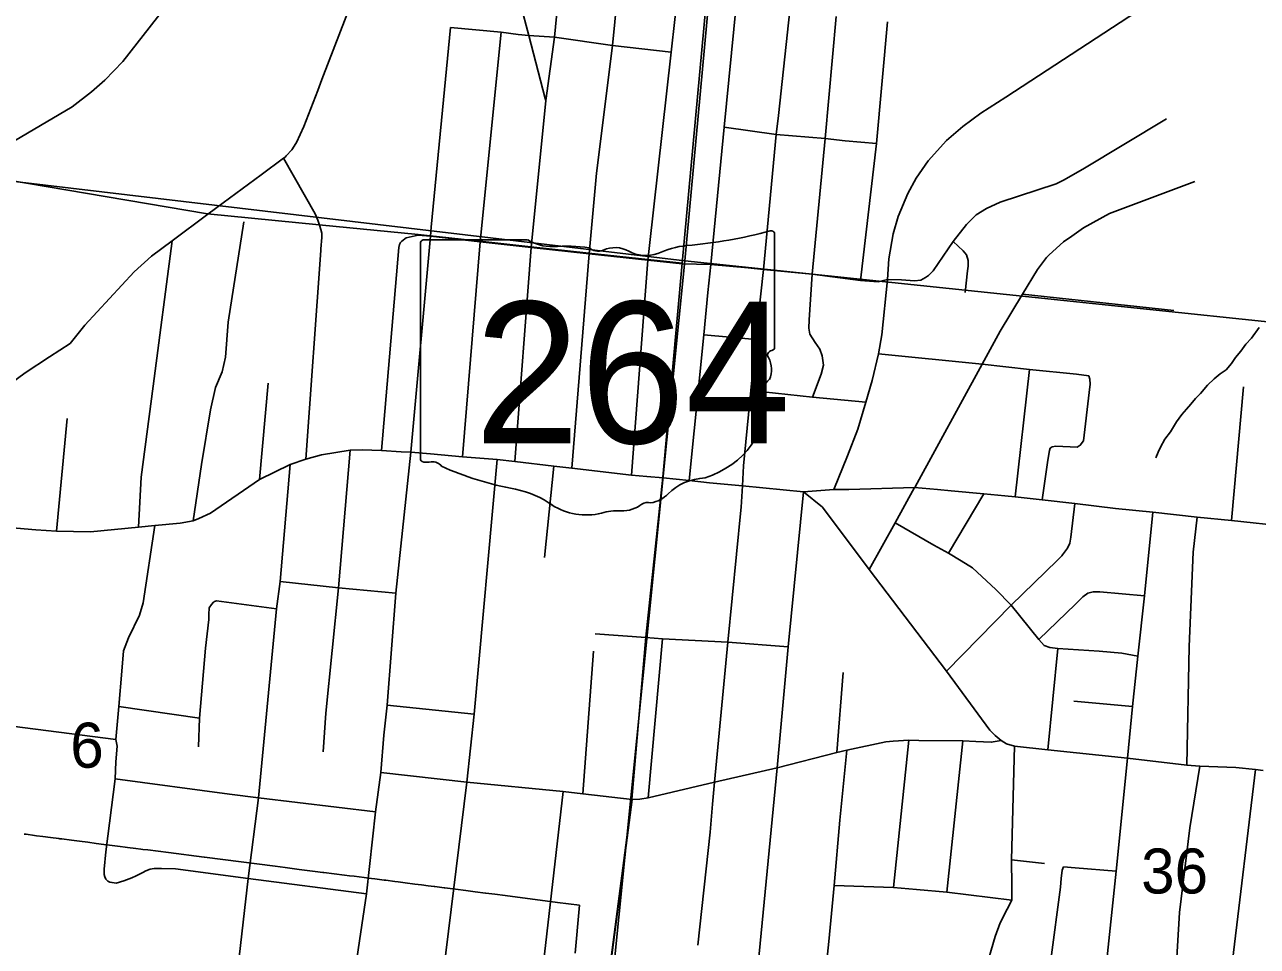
# Model space of a CAD drawing. Extents: x -8.2 to 38.5, y -0.1 to 21.9.
# Drawn here: x 2.928 to 4.076, y 14.657 to 15.515 of the extents above; entities that cross this region are included whole.
import ezdxf

# ---------------------------------------------------------------- set-up
doc = ezdxf.new("R2010")
doc.units = 0
for name, color, linetype in [('Default', 7, 'Continuous'), ('GM_X_Adjacent_County_Text', 7, 'Continuous'), ('GM_X_Airport_Location_Class_1', 7, 'Continuous'), ('GM_X_County_Road_Text', 7, 'Continuous'), ('GM_X_Major_River', 7, 'Continuous'), ('GM_X_Minor_River', 7, 'Continuous'), ('GM_X_Township_Subdivision_Text', 7, 'Continuous'), ('GM_X_Township_Text', 7, 'Continuous')]:
    doc.layers.add(name, color=color, linetype=linetype)

msp = doc.modelspace()

# ---------------------------------------------------------------- linework, layer by layer
at = {"layer": 'Default'}
for points in [[(3.6725, 16.67), (3.6705, 16.651), (3.6688, 16.6346), (3.6178, 16.1066), (3.5847, 15.7703), (3.5728, 15.6426), (3.5629, 15.5356), (3.5403, 15.2932), (3.5225, 15.0941), (3.5065, 14.9452), (3.4936, 14.7944), (3.4743, 14.647), (3.4653, 14.578), (3.4343, 14.2388), (3.4223, 14.1017), (3.4095, 13.9645), (4.8235, 13.9645)], [(2.8549, 15.3805), (3.0986, 15.3393), (3.2027, 15.3291), (3.2946, 15.3201), (3.3059, 15.3188), (3.3521, 15.3138), (3.3997, 15.3085), (3.4537, 15.3026), (3.5084, 15.2966), (3.5403, 15.2932), (3.5629, 15.5356), (3.5728, 15.6426), (3.5847, 15.7703), (3.6178, 16.1066), (3.6688, 16.6346)], [(3.4743, 14.647), (3.4936, 14.7944), (3.5065, 14.9452), (3.5225, 15.0941), (3.5403, 15.2932), (3.5084, 15.2966), (3.4537, 15.3026), (3.3997, 15.3085), (3.3521, 15.3138), (3.3059, 15.3188), (3.2946, 15.3201), (3.2027, 15.3291), (3.0986, 15.3393), (2.8549, 15.3805), (2.6397, 15.4029), (2.5303, 15.4164), (2.483, 15.4176), (2.4275, 15.419), (2.3952, 15.4189), (2.3338, 15.4222), (2.1974, 15.4294), (2.1644, 15.4316), (2.1634, 15.4317), (2.1634, 13.9645)], [(2.928, 14.7618), (2.9291, 14.7617), (2.9299, 14.7616), (2.9377, 14.7606), (2.9396, 14.7603), (2.9453, 14.7596), (2.9526, 14.7587), (2.9602, 14.7577), (2.9613, 14.7575), (2.9629, 14.7573), (2.9722, 14.7561), (2.9796, 14.7552), (2.9874, 14.7542), (2.995, 14.7532), (3.0023, 14.7522), (3.0098, 14.7512), (3.0173, 14.7503), (3.0219, 14.7497), (3.0243, 14.7494), (3.0318, 14.7484), (3.0366, 14.7478), (3.0385, 14.7476), (3.0432, 14.747), (3.0623, 14.7446), (3.0955, 14.7403), (3.0959, 14.7402), (3.1615, 14.7318), (3.1709, 14.7306), (3.1838, 14.7289), (3.1988, 14.7271), (3.2061, 14.7262), (3.2069, 14.7261), (3.2262, 14.7236), (3.2307, 14.7231), (3.2352, 14.7225), (3.2445, 14.7214), (3.2514, 14.7205), (3.2544, 14.7201), (3.2631, 14.719), (3.2645, 14.7189), (3.273, 14.7178), (3.276, 14.7174), (3.2805, 14.7168), (3.2825, 14.7165), (3.2917, 14.7153), (3.2977, 14.7145), (3.304, 14.7137), (3.3096, 14.713), (3.3101, 14.7129), (3.3188, 14.7118), (3.3193, 14.7117), (3.3196, 14.7117), (3.3294, 14.7104), (3.3392, 14.7092), (3.3477, 14.7081), (3.3574, 14.7069), (3.3576, 14.7069), (3.3662, 14.7058), (3.3758, 14.7045), (3.4243, 14.6982), (3.4448, 14.6955), (3.4445, 14.6922), (3.4409, 14.651)]]:
    msp.add_lwpolyline(points, dxfattribs=at)
at = {"layer": 'GM_X_Adjacent_County_Text'}
for points in [[(3.6356, 16.3025), (3.5428, 15.2954), (2.5334, 15.4148), (2.633, 16.4084)], [(4.6267, 16.1928), (4.5212, 15.1931), (3.5428, 15.2954), (3.6356, 16.3025)], [(2.5334, 15.4148), (3.5428, 15.2954), (3.4423, 14.2958), (2.4212, 14.4207)], [(3.5428, 15.2954), (4.5212, 15.1931), (4.4166, 14.1829), (3.4423, 14.2958)]]:
    msp.add_lwpolyline(points, close=True, dxfattribs=at)
at = {"layer": 'GM_X_Airport_Location_Class_1'}
msp.add_line((3.6533, 15.0805), (3.6817, 15.0826), dxfattribs=at)
for points in [[(2.9138, 15.0473), (2.9388, 15.0449), (2.9582, 15.0439), (2.9897, 15.0433), (3.0344, 15.0476), (3.0496, 15.049), (3.0732, 15.0513), (3.0853, 15.0535), (3.0906, 15.0555), (3.1013, 15.0607), (3.1471, 15.092), (3.1756, 15.106), (3.1903, 15.1108), (3.2047, 15.1148), (3.2313, 15.1192), (3.2427, 15.1196), (3.2607, 15.1189), (3.2789, 15.1178)], [(3.2789, 15.1178), (3.2879, 15.1173), (3.3063, 15.1159), (3.336, 15.113), (3.3683, 15.1104), (3.3847, 15.1086), (3.4211, 15.1044), (3.4376, 15.1023), (3.4933, 15.0959)], [(3.4933, 15.0959), (3.5074, 15.0948), (3.5227, 15.0936), (3.5469, 15.091), (3.5658, 15.0888), (3.5966, 15.086), (3.6533, 15.0805)], [(3.6817, 15.0826), (3.6954, 15.0826), (3.7568, 15.0845), (3.778, 15.0826)], [(3.778, 15.0826), (3.7907, 15.0814), (3.8213, 15.0787), (3.8406, 15.0766), (3.8502, 15.0757), (3.8755, 15.0729), (3.9058, 15.0697), (3.9437, 15.0648), (3.9786, 15.0615), (4.0197, 15.0569), (4.0518, 15.0538), (4.1035, 15.0481)]]:
    msp.add_lwpolyline(points, dxfattribs=at)
at = {"layer": 'GM_X_Major_River'}
for p, q in [((3.6265, 15.2153), (3.6265, 15.32)), ((3.2969, 15.3116), (3.2969, 15.1115)), ((3.3966, 15.3151), (3.3001, 15.3151)), ((3.6264, 15.2154), (3.6265, 15.2153))]:
    msp.add_line(p, q, dxfattribs=at)
for centre, major_axis, start_param, end_param in [((3.5091, 15.5879), (0.3495, 0), 4.814394, 5.042369), ((3.6228, 15.3205), (0.00367, 0), 6.141152, 7.989035), ((3.3007, 15.312), (0.00382, 0), 1.712693, 3.28349), ((3.4196, 15.3383), (0.037, 0), 4.042523, 4.731795), ((3.4319, 15.2027), (0.133, 0), 1.404758, 1.657858), ((3.4621, 15.3131), (0.0107, 0), 3.836095, 5.185415), ((3.4778, 15.29), (0.0222, 0), 0.950623, 2.079405), ((3.5536, 15.2539), (0.0703, 0), 1.699011, 2.107814), ((3.5065, 15.3217), (0.0267, 0), 4.081561, 5.145723), ((3.6226, 15.2149), (0.00393, 0), 5.05454, 6.418171), ((3.6256, 15.2077), (0.00568, 0), 1.883978, 3.671073), ((3.5895, 15.1944), (0.0341, 0), 5.934695, 6.695948), ((3.6396, 15.1715), (0.0248, 0), 2.387724, 3.262537), ((3.5286, 15.1582), (0.0874, 0), 5.101752, 6.440018), ((3.3007, 15.1111), (0.00385, 0), 3.00124, 4.508301), ((3.3013, 15.1315), (0.0294, 0), 4.665946, 4.897461), ((3.3073, 15.1), (0.0106, 0), 0.519207, 1.627899), ((3.4411, 15.2798), (0.2524, 0), 4.195997, 4.488961), ((3.5655, 15.0553), (0.0479, 0), 1.647645, 2.488434), ((3.3659, 15.0216), (0.079, 0), 0.823519, 1.323587), ((3.5048, 15.0921), (0.0282, 0), 4.937069, 5.64225), ((3.4513, 15.099), (0.0501, 0), 4.026481, 4.996735), ((3.4839, 15.084), (0.0267, 0), 4.691044, 5.507374), ((3.508, 15.0646), (0.00752, 0), 1.147584, 2.315152), ((3.4802, 15.0298), (0.0412, 0), 1.495662, 1.94098)]:
    msp.add_ellipse(centre, major_axis=major_axis, ratio=0.8, start_param=start_param, end_param=end_param, dxfattribs=at)
at = {"layer": 'GM_X_Minor_River'}
msp.add_lwpolyline([(4.0773, 15.2335), (4.0702, 15.2234), (4.0651, 15.2178), (4.0604, 15.2115), (4.0553, 15.2055), (4.0517, 15.1999), (4.0466, 15.194), (4.0411, 15.1903), (4.0357, 15.1855), (4.0294, 15.1796), (4.0228, 15.1721), (4.0181, 15.1673), (4.0138, 15.1621), (4.0098, 15.1573), (4.0055, 15.1524), (4.0004, 15.1457), (3.9948, 15.1364), (3.9897, 15.1296), (3.9857, 15.1221), (3.9836, 15.1172), (3.9812, 15.112)], dxfattribs=at)
at = {"layer": 'GM_X_Township_Subdivision_Text'}
for p, q in [((3.8572, 15.2644), (3.998, 15.2493)), ((3.5607, 15.2265), (3.6091, 15.2221)), ((3.8502, 15.0757), (3.8636, 15.1943)), ((3.1471, 15.092), (3.155, 15.1816)), ((4.0518, 15.0538), (4.0629, 15.1781)), ((2.9582, 15.0439), (2.9679, 15.1488)), ((3.4122, 15.0193), (3.4211, 15.1044)), ((3.7883, 15.0232), (3.8213, 15.0787)), ((3.5089, 14.7957), (3.522, 14.9436)), ((3.448, 14.7992), (3.4578, 14.9322)), ((3.8807, 14.8402), (3.8902, 14.9347)), ((3.6844, 14.8377), (3.6902, 14.9122)), ((3.0162, 14.8806), (3.0913, 14.8697)), ((3.2659, 14.8817), (3.3469, 14.8734)), ((3.905, 14.8856), (3.9597, 14.8807)), ((3.737, 14.712), (3.7515, 14.8492)), ((3.7867, 14.7077), (3.8017, 14.8485)), ((3.3141, 14.5989), (3.3401, 14.8102)), ((3.4051, 14.5862), (3.4296, 14.8014)), ((3.8469, 14.7378), (3.8775, 14.7345))]:
    msp.add_line(p, q, dxfattribs=at)
for points in [[(3.4933, 15.0959), (3.5086, 15.2961), (3.5096, 15.307), (3.5303, 15.4898), (3.5337, 15.5201), (3.5471, 15.6449), (3.5528, 15.7067), (3.5548, 15.7184), (3.5563, 15.7322), (3.5573, 15.7484), (3.5547, 15.7717)], [(3.4136, 15.4446), (3.4215, 15.5038), (3.4364, 15.6582)], [(3.4376, 15.1023), (3.4539, 15.3021), (3.4607, 15.377), (3.4755, 15.4959), (3.4907, 15.6506)], [(3.3847, 15.1086), (3.4, 15.308), (3.4136, 15.4446), (3.413, 15.4465), (3.3978, 15.5051), (3.39, 15.5345), (3.3858, 15.5462), (3.3784, 15.565), (3.3321, 15.6094), (3.3235, 15.6146), (3.2677, 15.648)], [(3.5469, 15.091), (3.5607, 15.2265), (3.5642, 15.2661), (3.5672, 15.2922), (3.5794, 15.4199), (3.5908, 15.5333), (3.6005, 15.6386), (3.6009, 15.6428), (3.6019, 15.6486)], [(3.5953, 15.0662), (3.5966, 15.086), (3.5976, 15.1046), (3.6044, 15.1749), (3.6091, 15.2221), (3.6161, 15.2874), (3.628, 15.4132), (3.6302, 15.4308), (3.6405, 15.5285), (3.65, 15.6286), (3.6507, 15.6346), (3.6509, 15.6387), (3.6508, 15.6416), (3.6492, 15.6437)], [(3.2879, 15.1173), (3.3061, 15.3183), (3.3069, 15.3268), (3.3249, 15.5126)], [(3.3249, 15.5126), (3.3721, 15.5082), (3.3878, 15.5061), (3.3978, 15.5051), (3.4215, 15.5038), (3.4755, 15.4959), (3.5303, 15.4898)], [(3.6836, 15.5229), (3.6735, 15.4093), (3.6614, 15.2829)], [(3.7063, 15.2771), (3.7212, 15.4047), (3.7315, 15.5181)], [(3.336, 15.113), (3.3524, 15.3132), (3.3721, 15.5082)], [(3.5794, 15.4199), (3.628, 15.4132), (3.6735, 15.4093), (3.6922, 15.4073), (3.7212, 15.4047)], [(3.7316, 15.2781), (3.7445, 15.2778), (3.7566, 15.2768), (3.7624, 15.2776), (3.7668, 15.2799), (3.7697, 15.2818), (3.7739, 15.286), (3.7786, 15.2931), (3.7925, 15.3135), (3.8052, 15.3294), (3.8087, 15.3331), (3.814, 15.3382), (3.8236, 15.3441), (3.8363, 15.3501), (3.8885, 15.3672), (3.8952, 15.3707), (3.9134, 15.3807), (3.9913, 15.4277)], [(3.2042, 15.3067), (3.2051, 15.3173), (3.2049, 15.3211), (3.204, 15.3247), (3.2029, 15.3286), (3.2012, 15.3333), (3.1987, 15.3392), (3.1693, 15.3909)], [(3.7145, 15.008), (3.7387, 15.0515), (3.7568, 15.0845), (3.7572, 15.0852), (3.8197, 15.1993), (3.8365, 15.2301), (3.8572, 15.2644), (3.871, 15.2874), (3.8794, 15.2985), (3.8821, 15.3012), (3.8954, 15.3131), (3.903, 15.3184), (3.914, 15.3261), (3.938, 15.3394), (4.0177, 15.3694)], [(3.0853, 15.0535), (3.093, 15.106), (3.1013, 15.1567), (3.106, 15.1774), (3.1122, 15.1921), (3.1155, 15.2057), (3.1179, 15.2383), (3.1324, 15.3319)], [(3.2607, 15.1189), (3.2766, 15.308), (3.2772, 15.3106), (3.2782, 15.3124), (3.2795, 15.3138), (3.2834, 15.3169)], [(3.2834, 15.3169), (3.2948, 15.3195), (3.3061, 15.3183), (3.3524, 15.3132), (3.4, 15.308), (3.4539, 15.3021), (3.5086, 15.2961), (3.5405, 15.2926), (3.5672, 15.2922), (3.6017, 15.2888), (3.6161, 15.2874), (3.6614, 15.2829), (3.7063, 15.2771), (3.7227, 15.276), (3.7316, 15.2781)], [(3.0344, 15.0476), (3.0369, 15.094), (3.0482, 15.1787), (3.0656, 15.3141)], [(3.1903, 15.1108), (3.204, 15.305), (3.2042, 15.3067)], [(3.8038, 15.2659), (3.8061, 15.2861), (3.8066, 15.2905), (3.8066, 15.2957), (3.805, 15.301), (3.802, 15.3047), (3.7925, 15.3135)], [(3.6616, 15.1687), (3.6697, 15.19), (3.6719, 15.1982), (3.6706, 15.2071), (3.6685, 15.2131), (3.6642, 15.2193), (3.6593, 15.2271), (3.6582, 15.2327), (3.6585, 15.2404), (3.6614, 15.2829)], [(3.7232, 15.209), (3.8197, 15.1993), (3.8636, 15.1943), (3.9073, 15.1899), (3.9188, 15.1885)], [(3.9081, 15.1219), (3.911, 15.1238), (3.9138, 15.128), (3.9192, 15.1729), (3.9201, 15.1806), (3.92, 15.1852), (3.9188, 15.1885)], [(3.6044, 15.1749), (3.6616, 15.1687), (3.7113, 15.164)], [(3.8755, 15.0729), (3.8809, 15.1099), (3.8824, 15.1188), (3.8829, 15.121), (3.8847, 15.1223), (3.8883, 15.123), (3.9081, 15.1219)], [(3.2062, 14.8384), (3.2087, 14.8743), (3.2205, 14.9911), (3.2313, 15.1192)], [(3.3401, 14.8102), (3.3469, 14.8734), (3.3683, 15.1104)], [(3.1258, 14.6283), (3.1364, 14.7204), (3.146, 14.7957), (3.1627, 14.9716), (3.1664, 14.9968), (3.1756, 15.106)], [(3.5688, 14.7898), (3.5705, 14.8101), (3.5828, 14.9406), (3.5951, 15.0633), (3.5953, 15.0662)], [(3.7864, 14.9134), (3.8465, 14.9748), (3.8893, 15.0166), (3.8938, 15.0209), (3.8944, 15.0217), (3.899, 15.0279), (3.9012, 15.0325), (3.9022, 15.0381), (3.9058, 15.0697)], [(3.9132, 14.4215), (3.9229, 14.5238), (3.9443, 14.7273), (3.9549, 14.8325), (3.9597, 14.8807), (3.9646, 14.9273), (3.9708, 14.9837), (3.9786, 15.0615)], [(4.01, 14.8261), (4.0124, 14.9363), (4.0161, 15.0243), (4.0197, 15.0569)], [(3.0058, 14.7181), (3.004, 14.7199), (3.003, 14.722), (3.0026, 14.7243), (3.0025, 14.7269), (3.0026, 14.7292), (3.0041, 14.7452), (3.0126, 14.8131), (3.0134, 14.8291), (3.0147, 14.8437), (3.0132, 14.8499), (3.0162, 14.8806), (3.0189, 14.9135), (3.0206, 14.9324), (3.0252, 14.9444), (3.0354, 14.9657), (3.0388, 14.977), (3.0496, 15.049)], [(3.9646, 14.9273), (3.9497, 14.9302), (3.9285, 14.932), (3.8902, 14.9347), (3.8826, 14.9354), (3.8774, 14.9374), (3.8724, 14.943), (3.8465, 14.9748), (3.8325, 14.9895), (3.8105, 15.0097), (3.8002, 15.0163), (3.7883, 15.0232), (3.7747, 15.0307), (3.7387, 15.0515)], [(3.1664, 14.9968), (3.2205, 14.9911), (3.274, 14.9861)], [(3.8724, 14.943), (3.9066, 14.976), (3.9132, 14.9828), (3.9181, 14.986), (3.9229, 14.9872), (3.9293, 14.9874), (3.9708, 14.9837)], [(3.0904, 14.8431), (3.0913, 14.8697), (3.0969, 14.9349), (3.0998, 14.9615), (3.0998, 14.9663), (3.1001, 14.9724)], [(3.1001, 14.9724), (3.1025, 14.9756), (3.1043, 14.9776), (3.1053, 14.9783), (3.1069, 14.9789), (3.1627, 14.9716)], [(3.4595, 14.9481), (3.5067, 14.9447), (3.522, 14.9436), (3.5828, 14.9406), (3.6391, 14.936)], [(2.6098, 14.8995), (2.6414, 14.8954), (2.7935, 14.8787), (2.8851, 14.8663), (3.0132, 14.8499)], [(3.2599, 14.819), (3.3401, 14.8102), (3.4296, 14.8014), (3.448, 14.7992), (3.4938, 14.7939), (3.501, 14.7943), (3.5089, 14.7957), (3.5705, 14.8101), (3.6289, 14.8236), (3.6844, 14.8377), (3.6936, 14.8399), (3.7301, 14.8477), (3.7369, 14.8484), (3.7515, 14.8492), (3.7608, 14.8488), (3.8017, 14.8485), (3.8137, 14.8479)], [(3.8137, 14.8479), (3.8281, 14.8473), (3.8373, 14.849)], [(3.6664, 14.5615), (3.677, 14.6619), (3.6818, 14.7141), (3.6872, 14.7749), (3.6936, 14.8399)], [(3.6883, 13.9645), (3.7093, 14.0685), (3.7248, 14.1598), (3.7609, 14.2545), (3.7638, 14.2665), (3.7836, 14.4615), (3.7847, 14.4733), (3.7867, 14.4884), (3.7997, 14.5378), (3.8072, 14.5697), (3.8217, 14.63), (3.8238, 14.6389), (3.828, 14.6539), (3.8316, 14.6666), (3.8365, 14.6792), (3.8428, 14.6919), (3.8471, 14.7004), (3.8471, 14.7133), (3.8469, 14.7378), (3.8497, 14.8437)], [(3.9881, 14.5156), (3.9993, 14.6209), (4.0032, 14.6889), (4.013, 14.7676), (4.0223, 14.8251)], [(3.0126, 14.8131), (3.1191, 14.799), (3.146, 14.7957), (3.2551, 14.7824)], [(3.4655, 14.5775), (3.4745, 14.6465), (3.4938, 14.7939)], [(3.555, 14.6585), (3.5665, 14.7635), (3.5688, 14.7898)], [(3.0058, 14.7181), (3.0076, 14.7172), (3.0099, 14.7166), (3.0135, 14.7162), (3.0207, 14.7182), (3.0281, 14.7212), (3.0321, 14.723), (3.0383, 14.7259), (3.0412, 14.7277), (3.0452, 14.7292), (3.049, 14.7297), (3.0558, 14.7299), (3.069, 14.7294), (3.1364, 14.7204), (3.2465, 14.7062)], [(3.8763, 14.6351), (3.878, 14.6364), (3.8803, 14.6383), (3.8822, 14.6406), (3.8834, 14.6448), (3.8925, 14.7124), (3.8932, 14.7205), (3.894, 14.7281), (3.8952, 14.7313)], [(3.8952, 14.7313), (3.9061, 14.7303), (3.9443, 14.7273)], [(3.6818, 14.7141), (3.737, 14.712), (3.7585, 14.7101), (3.7867, 14.7077), (3.8471, 14.7004)]]:
    msp.add_lwpolyline(points, dxfattribs=at)
at = {"layer": 'GM_X_Township_Text'}
for p, q in [((3.6391, 14.936), (3.6533, 15.0805)), ((3.6533, 15.0805), (3.6817, 15.0826)), ((3.6289, 14.8236), (3.6391, 14.936)), ((3.6042, 14.5677), (3.6289, 14.8236))]:
    msp.add_line(p, q, dxfattribs=at)
for points in [[(3.2052, 15.4644), (3.2277, 15.523), (3.2563, 15.6125), (3.2642, 15.6393), (3.2677, 15.648), (3.2711, 15.6561), (3.278, 15.6749)], [(2.8599, 15.3804), (2.8648, 15.3808), (2.8657, 15.3809), (2.8738, 15.3833), (2.8891, 15.3897), (2.9726, 15.4387), (2.9907, 15.4527), (3.0031, 15.4637), (3.0199, 15.4811), (3.0709, 15.5469), (3.0887, 15.5764), (3.092, 15.5858), (3.0982, 15.5928), (3.1082, 15.6003)], [(3.6817, 15.0826), (3.6943, 15.114), (3.7038, 15.1389), (3.7113, 15.164), (3.7174, 15.184), (3.7232, 15.209), (3.7264, 15.2266), (3.7316, 15.2781), (3.7327, 15.2973), (3.7369, 15.3207), (3.7416, 15.3367), (3.7503, 15.358), (3.7581, 15.3724), (3.7694, 15.3887), (3.7863, 15.4074), (3.8015, 15.4205), (3.8183, 15.4329), (3.8417, 15.4478), (3.9562, 15.5227), (3.9767, 15.5343), (3.9996, 15.544), (4.0311, 15.5571), (4.091, 15.5821)], [(3.181, 15.4048), (3.1814, 15.4055), (3.1883, 15.4205), (3.2012, 15.4541), (3.2052, 15.4644)], [(3.1693, 15.3909), (3.1705, 15.3918), (3.1718, 15.3932), (3.1771, 15.3988), (3.181, 15.4048)], [(3.1133, 15.3494), (3.1485, 15.3755), (3.1693, 15.3909)], [(2.8635, 15.119), (2.8845, 15.1483), (2.9006, 15.1695), (2.9099, 15.1772), (2.9288, 15.1911), (2.9516, 15.206), (2.9708, 15.2184), (2.9845, 15.2355), (3.0305, 15.2851), (3.0465, 15.2999), (3.0656, 15.3141), (3.0988, 15.3388), (3.1133, 15.3494)], [(3.2024, 14.3243), (3.2061, 14.3542), (3.2128, 14.4071), (3.218, 14.4549), (3.2325, 14.6103), (3.2465, 14.7062), (3.2551, 14.7824), (3.2599, 14.819), (3.2629, 14.854), (3.2659, 14.8817), (3.274, 14.9861), (3.2879, 15.1173)], [(3.6533, 15.0805), (3.6709, 15.0663), (3.7145, 15.008), (3.7864, 14.9134), (3.8268, 14.8585), (3.8316, 14.8536), (3.8373, 14.849), (3.8424, 14.8458), (3.8497, 14.8437), (3.8807, 14.8402), (3.9549, 14.8325), (4.01, 14.8261), (4.0223, 14.8251), (4.0557, 14.8239), (4.0741, 14.8219), (4.0813, 14.821)], [(4.05, 14.6249), (4.0525, 14.6438), (4.0741, 14.8219)]]:
    msp.add_lwpolyline(points, dxfattribs=at)

# ---------------------------------------------------------------- texts
at = {"layer": 'GM_X_County_Road_Text'}
for s, height, p in [('6', 0.0419, (2.9709, 14.8236)), ('36', 0.04186, (3.9676, 14.7065))]:
    msp.add_text(s, height=height, rotation=0, dxfattribs=at).set_placement(p)
at = {"layer": 'GM_X_Major_River'}
msp.add_text('264', height=0.13184, dxfattribs=at).set_placement((3.3472, 15.1256))

doc.saveas('drawing.dxf')
